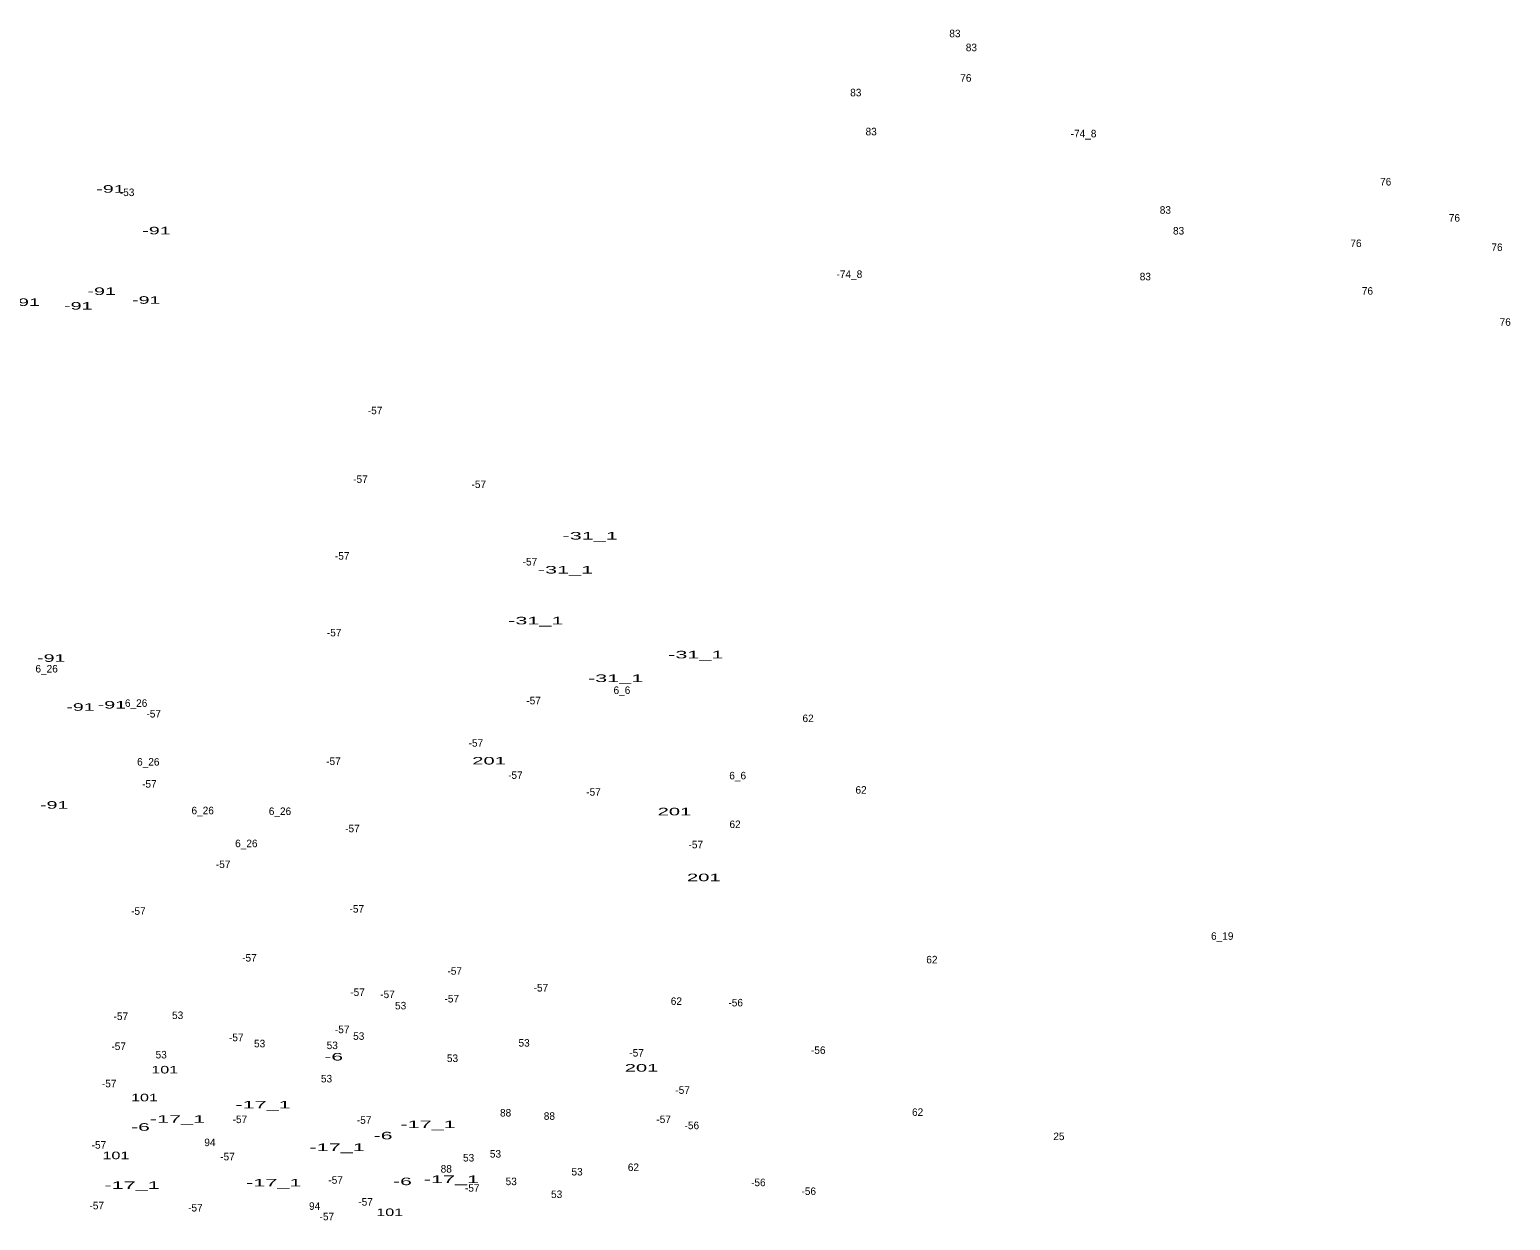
# Model space of a CAD drawing. Extents: x -659624 to -656248, y -1006345 to -1003555.
# Drawn here: x -657087 to -656300, y -1004233 to -1003600 of the extents above; entities that cross this region are included whole.
import ezdxf
from ezdxf.enums import TextEntityAlignment as Align

# ---------------------------------------------------------------- set-up
doc = ezdxf.new("R2010")
doc.units = 0
doc.header["$LTSCALE"] = 1.6
doc.layers.add('24', color=7, linetype='Continuous')

msp = doc.modelspace()

# ---------------------------------------------------------------- texts
at = {"layer": '24'}
for s, p in [('83', (-656595.507, -1003604.54)), ('83', (-656586.767, -1003611.96)), ('76', (-656589.698, -1003628.16)), ('83', (-656648.187, -1003635.93)), ('83', (-656640.017, -1003656.67)), ('-74_8', (-656527.162, -1003657.74)), ('76', (-656366.608, -1003683.33)), ('-53', (-657035.385, -1003688.95)), ('83', (-656483.687, -1003698.34)), ('76', (-656330.098, -1003702.54)), ('83', (-656476.657, -1003709.38)), ('76', (-656382.398, -1003716.05)), ('76', (-656307.468, -1003718.14)), ('-74_8', (-656651.592, -1003732.46)), ('83', (-656494.337, -1003733.73)), ('76', (-656376.308, -1003741.35)), ('76', (-656303.088, -1003757.9)), ('-57', (-656903.641, -1003804.9)), ('-57', (-656911.411, -1003841.4)), ('-57', (-656848.521, -1003844.12)), ('-57', (-656921.111, -1003882.18)), ('-57', (-656821.341, -1003885.29)), ('-57', (-656925.381, -1003922.96)), ('6_26', (-657078.166, -1003942.15)), ('6_26', (-657030.616, -1003960.41)), ('-57', (-656819.401, -1003959.07)), ('6_6', (-656772.467, -1003953.54)), ('-57', (-657021.261, -1003966.07)), ('62', (-656673.543, -1003968.51)), ('-57', (-656850.071, -1003981.6)), ('6_26', (-657024.156, -1003991.61)), ('-57', (-656925.771, -1003991.31)), ('-57', (-656829.101, -1003998.69)), ('6_6', (-656710.947, -1003998.92)), ('-57', (-657023.591, -1004003.35)), ('-57', (-656787.561, -1004007.62)), ('62', (-656645.393, -1004006.56)), ('6_26', (-656995.246, -1004017.49)), ('6_26', (-656954.166, -1004017.87)), ('-57', (-656915.671, -1004027.04)), ('62', (-656712.343, -1004024.83)), ('6_26', (-656972.046, -1004034.99)), ('-57', (-656733.221, -1004035.58)), ('-57', (-656984.381, -1004046.07)), ('-57', (-656913.341, -1004069.75)), ('-57', (-657029.421, -1004070.92)), ('6_19', (-656453.47, -1004084.2)), ('-57', (-656970.411, -1004095.77)), ('62', (-656607.743, -1004096.74)), ('-57', (-656861.321, -1004102.76)), ('-57', (-656912.951, -1004114.03)), ('-57', (-656897.041, -1004115.19)), ('-57', (-656862.881, -1004117.52)), ('-57', (-656815.521, -1004111.7)), ('53', (-656890.057, -1004121.19)), ('62', (-656743.533, -1004118.81)), ('-56', (-656712.01, -1004119.61)), ('-57', (-657038.731, -1004126.84)), ('53', (-657008.547, -1004126.32)), ('-57', (-656921.111, -1004133.83)), ('-57', (-656977.401, -1004138.1)), ('53', (-656964.987, -1004141.35)), ('53', (-656912.307, -1004137.36)), ('53', (-656824.447, -1004140.97)), ('-57', (-657039.891, -1004142.78)), ('53', (-657017.287, -1004147.25)), ('53', (-656926.387, -1004142.3)), ('53', (-656862.487, -1004149.15)), ('-57', (-656764.661, -1004146.26)), ('-56', (-656668.14, -1004144.86)), ('-57', (-657044.941, -1004162.59)), ('53', (-656929.427, -1004160)), ('-57', (-656740.201, -1004166.07)), ('88', (-656834.277, -1004178.12)), ('88', (-656811.017, -1004179.86)), ('62', (-656615.343, -1004177.79)), ('-57', (-656975.451, -1004181.62)), ('-57', (-656909.461, -1004181.99)), ('-57', (-656750.301, -1004181.6)), ('-56', (-656735.3, -1004184.86)), ('-57', (-657050.381, -1004195.21)), ('94', (-656991.397, -1004193.88)), ('25', (-656540.257, -1004190.66)), ('-57', (-656982.051, -1004201.42)), ('53', (-656853.927, -1004202.04)), ('53', (-656839.667, -1004199.95)), ('88', (-656865.807, -1004207.93)), ('53', (-656796.307, -1004209.46)), ('62', (-656766.353, -1004207.09)), ('-57', (-656924.601, -1004213.85)), ('-57', (-656852.011, -1004218.1)), ('53', (-656831.297, -1004214.6)), ('-56', (-656699.98, -1004215.15)), ('-56', (-656673.19, -1004219.81)), ('-57', (-657051.541, -1004227.44)), ('94', (-656935.747, -1004227.73)), ('-57', (-656908.681, -1004225.49)), ('53', (-656807.147, -1004221.45)), ('-57', (-656999.131, -1004228.61)), ('-57', (-656929.261, -1004233.27))]:
    msp.add_text(s, height=4, dxfattribs=at).set_placement(p, align=Align.CENTER)
for s, width, p in [('-91', 1.95, (-657044.255, -1003687.15)), ('-91', 1.95, (-657019.805, -1003709.28)), ('-91', 1.95, (-657089.285, -1003747.34)), ('-91', 1.95, (-657048.915, -1003741.51)), ('-91', 1.95, (-657025.245, -1003746.18)), ('-91', 1.95, (-657061.345, -1003749.28)), ('-31_1', 2.15, (-656789.317, -1003871.48)), ('-31_1', 2.15, (-656802.437, -1003889.54)), ('-31_1', 2.15, (-656818.227, -1003916.56)), ('-91', 1.95, (-657075.705, -1003936.47)), ('-31_1', 2.15, (-656733.207, -1003934.63)), ('-31_1', 2.15, (-656775.817, -1003947.19)), ('-91', 1.95, (-657060.175, -1003962.48)), ('-91', 1.95, (-657043.485, -1003961.32)), ('201', 2, (-656843.064, -1003991.04)), ('-91', 1.95, (-657074.145, -1004014.52)), ('201', 2, (-656744.554, -1004018.05)), ('201', 2, (-656728.954, -1004053.06)), ('-6', 2.1, (-656925.609, -1004148.36)), ('101', 1.6, (-657015.41, -1004155.23)), ('201', 2, (-656762.044, -1004154.27)), ('101', 1.6, (-657026.18, -1004170.04)), ('-17_1', 2.15, (-656963.153, -1004173.81)), ('-6', 2.1, (-657028.299, -1004185.68)), ('-17_1', 2.15, (-657008.603, -1004181.42)), ('-17_1', 2.15, (-656875.473, -1004184.28)), ('-17_1', 2.15, (-656923.773, -1004196.45)), ('-6', 2.1, (-656899.359, -1004190.25)), ('101', 1.6, (-657041.36, -1004200.81)), ('-17_1', 2.15, (-657032.753, -1004216.62)), ('-17_1', 2.15, (-656957.443, -1004215.29)), ('-6', 2.1, (-656889.089, -1004214.6)), ('-17_1', 2.15, (-656863.113, -1004213.46)), ('101', 1.6, (-656895.84, -1004231.01))]:
    msp.add_text(s, height=4, dxfattribs=dict(at, width=width)).set_placement(p, align=Align.CENTER)

doc.saveas('drawing.dxf')
